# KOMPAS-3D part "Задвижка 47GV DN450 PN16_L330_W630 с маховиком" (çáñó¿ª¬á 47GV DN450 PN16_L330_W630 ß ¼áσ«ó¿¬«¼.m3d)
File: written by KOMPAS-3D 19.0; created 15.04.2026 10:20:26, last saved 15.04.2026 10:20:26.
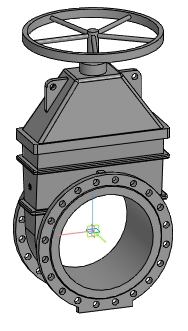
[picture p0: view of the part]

Document properties: Автор: Евгений; Полное имя файла: Z:\3.Личные\kachalov\3d для проектировщиков\2.1 Тип 47GV, 47GV.Z\Задвижка 47GV_DN40-DN600\stp_Задвижка 47GV\Задвижка 47GV DN450 PN16_L330_W630 с маховиком.m3d

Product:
- Part/product: Задвижка 47GV DN450 PN16_L330_W630 с маховиком

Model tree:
1. Операция без истории:1  (labels: Задвижка 47GV DN450 PN16_L330_W630 с маховиком)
